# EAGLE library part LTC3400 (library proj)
Linear LTC3400 voltage boost converter
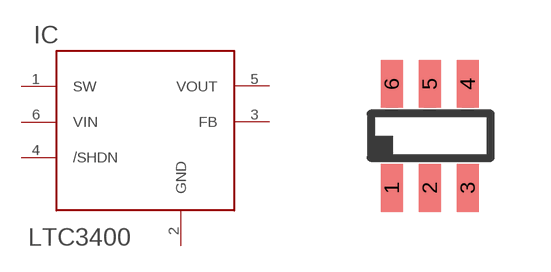
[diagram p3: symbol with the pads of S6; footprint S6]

Designator prefix IC

## LTC3400  [S6]
1  SW  pas
2  GND  pwr
3  FB  pas
4  /SHDN  in
5  VOUT  pas
6  VIN  pwr

## Footprint S6 (pad centres in mm)
Linear 6 pin TSOT-23
smd 0.55 x 1.2: 1 -0.975,-1.3; 2 -0.025,-1.3; 3 0.925,-1.3; 4 0.925,1.3; 5 -0.025,1.3; 6 -0.975,1.3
